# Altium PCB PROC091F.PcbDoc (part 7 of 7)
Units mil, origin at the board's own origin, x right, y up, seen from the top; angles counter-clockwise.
Board outline 3590.95 x 906.17 mil, 8 copper layers (Top Layer, GND1, Sig1, PWR1, PWR2, Sig2, GND2, Bottom Layer), stack 63.146 mil thick; 420 components, 316 nets, 1432 pads, 774 vias.
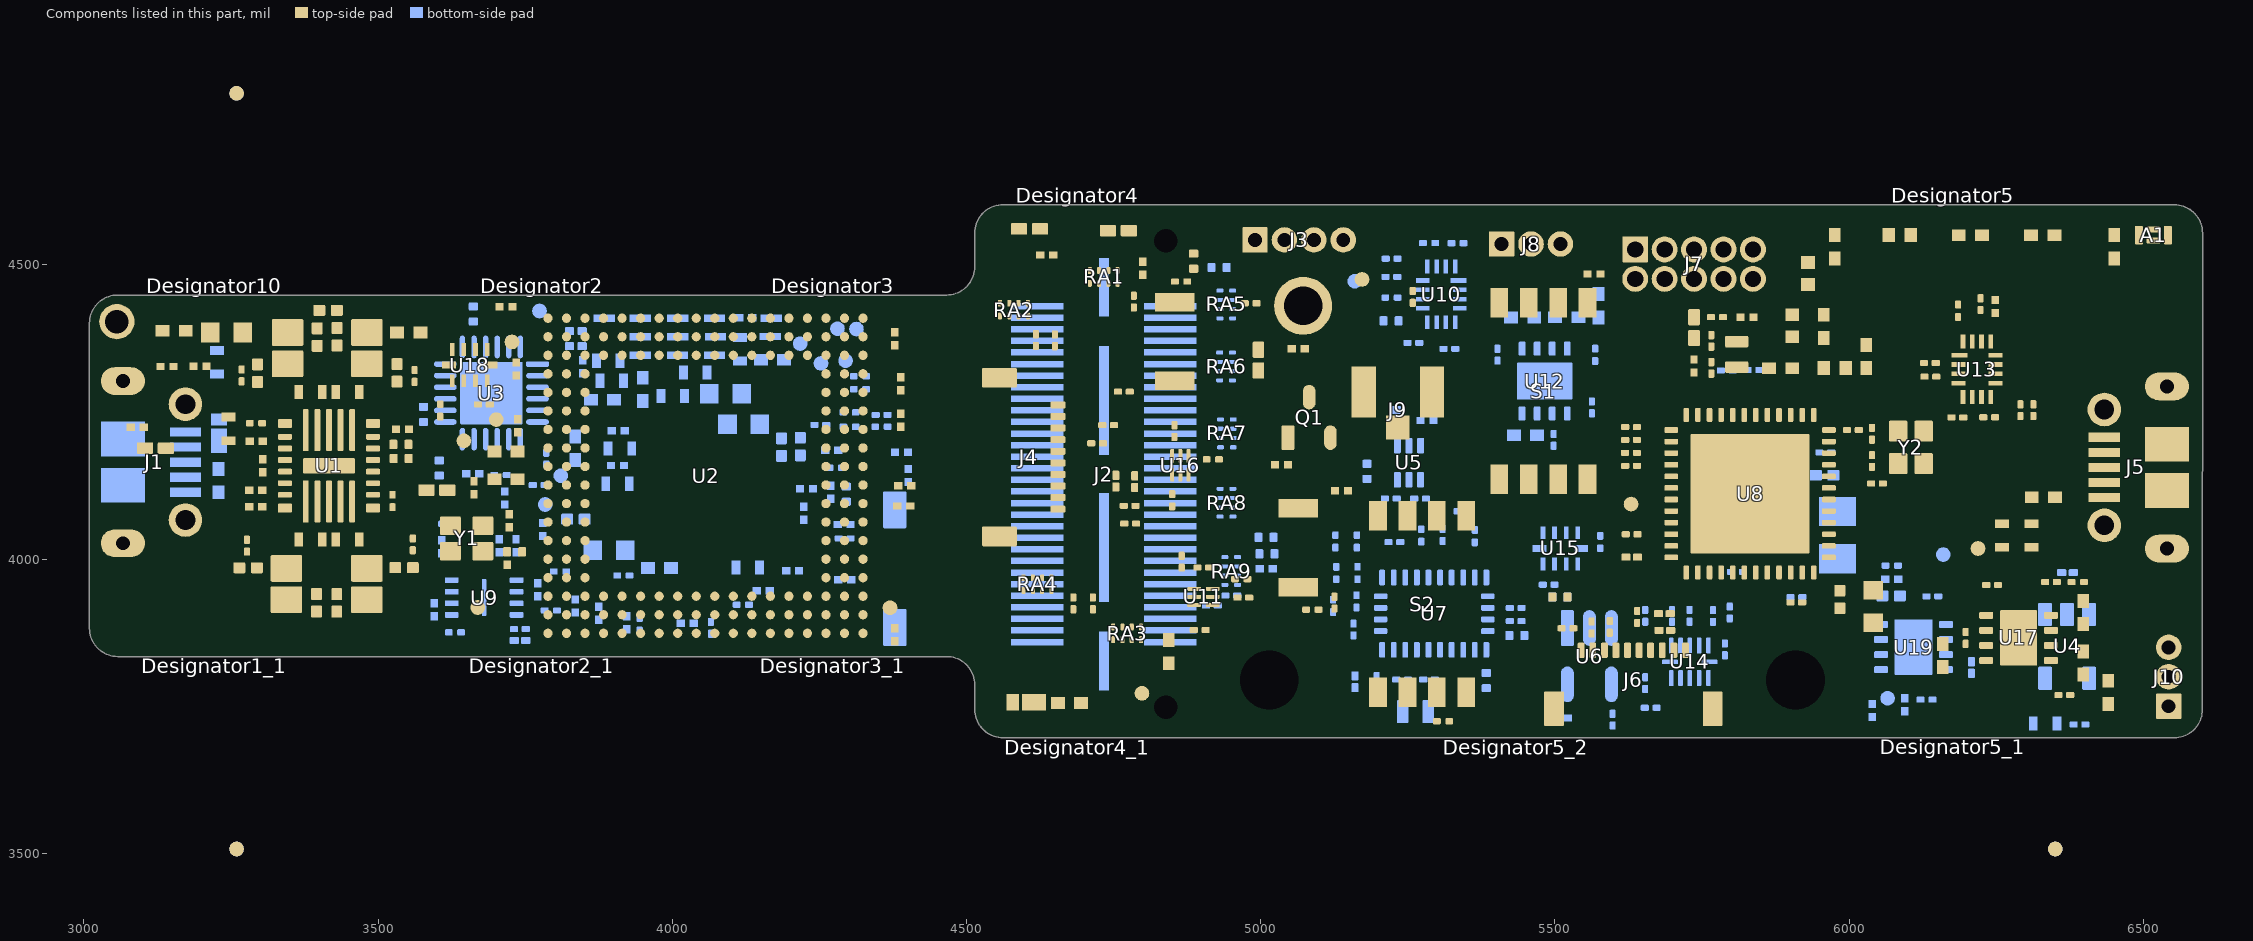
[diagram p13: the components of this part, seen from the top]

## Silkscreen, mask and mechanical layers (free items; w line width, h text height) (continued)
M12 Stackup:
  drawing of 503 lines, arcs and shapes, not listed
  text "Layer" at 8.08,2124.8 h60
  text "Name" at 417.99,2124.8 h60
  text "Material" at 1347.73,2124.8 h60
  text "Thickness" at 2207.5,2124.8 h60
  text "Constant" at 2857.34,2124.8 h60
  text "Board Layer Stack" at 3427.2,2124.8 h60
  text "1" at 8.08,2004.8 h60
  text "Top Overlay" at 417.99,2004.8 h60
  text "2" at 8.08,1884.8 h60
  text "Top Solder" at 417.99,1884.8 h60
  text "Solder Resist" at 1347.73,1884.8 h60
  text "0.50mil" at 2207.5,1884.8 h60
  text "3.5" at 2857.34,1884.8 h60
  text "3" at 8.08,1764.8 h60
  text "Top Layer" at 417.99,1764.8 h60
  text "Copper" at 1347.73,1764.8 h60
  text "1.37mil" at 2207.5,1764.8 h60
  text "4" at 8.08,1644.8 h60
  text "Dielectric1" at 417.99,1644.8 h60
  text "FR-4 High Tg" at 1347.73,1644.8 h60
  text "3.70mil" at 2207.5,1644.8 h60
  text "4.2" at 2857.34,1644.8 h60
  text "5" at 8.08,1524.8 h60
  text "GND1" at 417.99,1524.8 h60
  text "Copper" at 1347.73,1524.8 h60
  text "2.40mil" at 2207.5,1524.8 h60
  text "6" at 8.08,1404.8 h60
  text "Dielectric3" at 417.99,1404.8 h60
  text "FR-4 High Tg" at 1347.73,1404.8 h60
  text "4.50mil" at 2207.5,1404.8 h60
  text "4.2" at 2857.34,1404.8 h60
  text "7" at 8.08,1284.8 h60
  text "Sig1" at 417.99,1284.8 h60
  text "Copper" at 1347.73,1284.8 h60
  text "1.20mil" at 2207.5,1284.8 h60
  text "8" at 8.08,1164.8 h60
  text "Dielectric2" at 417.99,1164.8 h60
  text "FR-4 High Tg" at 1347.73,1164.8 h60
  text "12.00mil" at 2207.5,1164.8 h60
  text "4.2" at 2857.34,1164.8 h60
  text "9" at 8.08,1044.8 h60
  text "PWR1" at 417.99,1044.8 h60
  text "Copper" at 1347.73,1044.8 h60
  text "2.40mil" at 2207.5,1044.8 h60
  text "10" at 8.08,924.8 h60
  text "Dielectric4" at 417.99,924.8 h60
  text "FR-4 High Tg" at 1347.73,924.8 h60
  text "8.00mil" at 2207.5,924.8 h60
  text "4.2" at 2857.34,924.8 h60
  text "11" at 8.08,804.8 h60
  text "PWR2" at 417.99,804.8 h60
  text "Copper" at 1347.73,804.8 h60
  text "2.40mil" at 2207.5,804.8 h60
  text "12" at 8.08,684.8 h60
  text "Dielectric5" at 417.99,684.8 h60
  text "FR-4 High Tg" at 1347.73,684.8 h60
  text "12.00mil" at 2207.5,684.8 h60
  text "4.2" at 2857.34,684.8 h60
  text "13" at 8.08,564.8 h60
  text "Sig2" at 417.99,564.8 h60
  text "Copper" at 1347.73,564.8 h60
  text "1.20mil" at 2207.5,564.8 h60
  text "14" at 8.08,444.8 h60
  text "Dielectric8" at 417.99,444.8 h60
  text "FR-4 High Tg" at 1347.73,444.8 h60
  text "4.50mil" at 2207.5,444.8 h60
  text "4.2" at 2857.34,444.8 h60
  text "15" at 8.08,324.8 h60
  text "GND2" at 417.99,324.8 h60
  text "Copper" at 1347.73,324.8 h60
  text "2.40mil" at 2207.5,324.8 h60
  text "16" at 8.08,204.8 h60
  text "Dielectric9" at 417.99,204.8 h60
  text "FR-4 High Tg" at 1347.73,204.8 h60
  text "3.70mil" at 2207.5,204.8 h60
  text "4.2" at 2857.34,204.8 h60
  text "17" at 8.08,84.8 h60
  text "Bottom Layer" at 417.99,84.8 h60
  text "Copper" at 1347.73,84.8 h60
  text "1.37mil" at 2207.5,84.8 h60
  text "18" at 8.08,-35.2 h60
  text "Bottom Solder" at 417.99,-35.2 h60
  text "Solder Resist" at 1347.73,-35.2 h60
  text "0.50mil" at 2207.5,-35.2 h60
  text "3.5" at 2857.34,-35.2 h60
  text "19" at 8.08,-155.2 h60
  text "Bottom Overlay" at 417.99,-155.2 h60
  text ".Layer_Name" at 577,-858.49 h60
M13 Component Bodies Top:
  text ".Layer_Name" at 577,-858.49 h60
M14 Component Bodies Bottom:
  text ".Layer_Name" at 577,-858.49 h60
M15 Courtyards Top:
  text ".Layer_Name" at 577,-858.49 h60
M16 Courtyards Bottom:
  text ".Layer_Name" at 577,-858.49 h60
Drill Drawing:
  circle w10: c7603.25,4723.45 r16.58
  circle w10: c7603.25,4723.45 r27.63
  circle w10: c7603.25,3355.93 r27.63
  lines w10: 7575.63,3452.62 7603.25,3466.44 7630.88,3452.62 7617.07,3480.25 7630.88,3507.88 7603.25,3494.06 7575.63,3507.88 7589.44,3480.25 7575.63,3452.62 ; 7575.63,3590.76 7589.44,3590.76 7603.25,3576.94 7617.07,3590.76 7630.88,3590.76 7617.07,3604.57 7630.88,3618.38 7617.07,3618.38 7603.25,3632.2 7589.44,3618.38 7575.63,3618.38 7589.44,3604.57 7575.63,3590.76 ; 7575.63,3715.08 7589.44,3715.08 7589.44,3701.26 7617.07,3701.26 7617.07,3715.08 7630.88,3715.08 7630.88,3742.7 7617.07,3742.7 7617.07,3756.52 7589.44,3756.52 7589.44,3742.7 7575.63,3742.7 7575.63,3715.08 ; 7575.63,3825.58 7603.25,3839.4 7630.88,3825.58 7617.07,3853.21 7630.88,3880.84 7603.25,3867.02 7575.63,3880.84 7589.44,3853.21 7575.63,3825.58 ; 7575.63,3977.53 7603.25,3949.9 7630.88,3977.53 7603.25,4005.16 7575.63,3977.53 ; 7575.63,4088.04 7589.44,4088.04 7589.44,4074.22 7617.07,4074.22 7617.07,4088.04 7630.88,4088.04 7630.88,4115.66 7617.07,4115.66 7617.07,4129.48 7589.44,4129.48 7589.44,4115.66 7575.63,4115.66 7575.63,4088.04 ; 7575.63,4253.8 7630.88,4253.8 7603.25,4198.54 7575.63,4253.8 ; 7575.63,4322.86 7575.63,4336.68 7589.44,4350.49 7575.63,4364.3 7575.63,4378.12 7589.44,4378.12 7603.25,4364.3 7617.07,4378.12 7630.88,4378.12 7630.88,4364.3 7617.07,4350.49 7630.88,4336.68 7630.88,4322.86 7617.07,4322.86 7603.25,4336.68 7589.44,4322.86 7575.63,4322.86 ; 7575.63,4447.18 7630.88,4447.18 7630.88,4502.44 7575.63,4502.44 7575.63,4447.18 ; 7575.63,4626.76 7630.88,4626.76 7603.25,4571.5 7575.63,4626.76 ; 7575.63,4820.14 7630.88,4820.14 7630.88,4875.4 7575.63,4875.4 7575.63,4820.14 ; 7586.68,3463.67 7603.25,3471.96 7619.83,3463.67 7611.54,3480.25 7619.83,3496.83 7603.25,3488.54 7586.68,3496.83 7594.97,3480.25 7586.68,3463.67 ; 7586.68,4093.56 7594.97,4093.56 7594.97,4085.27 7611.54,4085.27 7611.54,4093.56 7619.83,4093.56 7619.83,4110.14 7611.54,4110.14 7611.54,4118.43 7594.97,4118.43 7594.97,4110.14 7586.68,4110.14 7586.68,4093.56 ; 7586.68,4615.71 7619.83,4615.71 7603.25,4582.55 7586.68,4615.71 ; 7586.68,4831.19 7619.83,4831.19 7619.83,4864.35 7586.68,4864.35 7586.68,4831.19
  lines w12: 7525.54,3291.01 10757.03,3291.01 ; 7525.54,4907.17 10757.03,4907.17 ; 7863.4,3166.69 7863.4,5031.49 ; 8195.4,3166.69 8195.4,5031.49 ; 8831.96,3166.69 8831.96,5031.49 ; 9091.1,3166.69 9091.1,5031.49 ; 9466.26,3166.69 9466.26,5031.49 ; 10190.59,3166.69 10190.59,5031.49 ; 7525.54,3166.69 10757.03,3166.69 10757.03,5031.49 7525.54,5031.49 7525.54,3166.69
  text "Symbol" at 7600.13,4944.46 h72
  text "Quantity" at 7900.7,4944.46 h72
  text "Finished Hole Size" at 8232.7,4944.46 h72
  text "Plated" at 8869.26,4944.46 h72
  text "Hole Type" at 9128.4,4944.46 h72
  text "Drill Layer Pair" at 9503.56,4944.46 h72
  text "Hole Tolerance" at 10227.89,4944.46 h72
  text "36" at 7900.7,4820.14 h60
  text "7.87mil" at 8232.7,4820.14 h60
  text "PTH" at 8869.26,4820.14 h60
  text "Round" at 9128.4,4820.14 h60
  text "Top Layer - Bottom Layer" at 9503.56,4820.14 h60
  text "626" at 7900.7,4695.82 h60
  text "8.00mil" at 8232.7,4695.82 h60
  text "PTH" at 8869.26,4695.82 h60
  text "Round" at 9128.4,4695.82 h60
  text "Top Layer - Bottom Layer" at 9503.56,4695.82 h60
  text "112" at 7900.7,4571.5 h60
  text "8.00mil" at 8232.7,4571.5 h60
  text "PTH" at 8869.26,4571.5 h60
  text "Round" at 9128.4,4571.5 h60
  text "Top Layer - Bottom Layer" at 9503.56,4571.5 h60
  text "+/-3.00mil" at 10227.89,4571.5 h60
  text "10" at 7900.7,4447.18 h60
  text "23.62mil" at 8232.7,4447.18 h60
  text "PTH" at 8869.26,4447.18 h60
  text "Round" at 9128.4,4447.18 h60
  text "Top Layer - Bottom Layer" at 9503.56,4447.18 h60
  text "4" at 7900.7,4322.86 h60
  text "23.62mil" at 8232.7,4322.86 h60
  text "PTH" at 8869.26,4322.86 h60
  text "Slot" at 9128.4,4322.86 h60
  text "Top Layer - Bottom Layer" at 9503.56,4322.86 h60
  text "10" at 7900.7,4198.54 h60
  text "27.56mil" at 8232.7,4198.54 h60
  text "PTH" at 8869.26,4198.54 h60
  text "Round" at 9128.4,4198.54 h60
  text "Top Layer - Bottom Layer" at 9503.56,4198.54 h60
  text "33" at 7900.7,4074.22 h60
  text "32.00mil" at 8232.7,4074.22 h60
  text "NPTH" at 8869.26,4074.22 h60
  text "Round" at 9128.4,4074.22 h60
  text "Top Layer - Bottom Layer" at 9503.56,4074.22 h60
  text "4" at 7900.7,3949.9 h60
  text "33.47mil" at 8232.7,3949.9 h60
  text "PTH" at 8869.26,3949.9 h60
  text "Round" at 9128.4,3949.9 h60
  text "Top Layer - Bottom Layer" at 9503.56,3949.9 h60
  text "1" at 7900.7,3825.58 h60
  text "40.00mil" at 8232.7,3825.58 h60
  text "PTH" at 8869.26,3825.58 h60
  text "Round" at 9128.4,3825.58 h60
  text "Top Layer - Bottom Layer" at 9503.56,3825.58 h60
  text "2" at 7900.7,3701.26 h60
  text "40.16mil" at 8232.7,3701.26 h60
  text "NPTH" at 8869.26,3701.26 h60
  text "Round" at 9128.4,3701.26 h60
  text "Top Layer - Bottom Layer" at 9503.56,3701.26 h60
  text "1" at 7900.7,3576.94 h60
  text "64.96mil" at 8232.7,3576.94 h60
  text "PTH" at 8869.26,3576.94 h60
  text "Round" at 9128.4,3576.94 h60
  text "Top Layer - Bottom Layer" at 9503.56,3576.94 h60
  text "4" at 7900.7,3452.62 h60
  text "88.00mil" at 8232.7,3452.62 h60
  text "NPTH" at 8869.26,3452.62 h60
  text "Round" at 9128.4,3452.62 h60
  text "Top Layer - Bottom Layer" at 9503.56,3452.62 h60
  text "+/-3.00mil" at 10227.89,3452.62 h60
  text "2" at 7900.7,3328.3 h60
  text "100.00mil" at 8232.7,3328.3 h60
  text "NPTH" at 8869.26,3328.3 h60
  text "Round" at 9128.4,3328.3 h60
  text "Top Layer - Bottom Layer" at 9503.56,3328.3 h60
  text "+/-3.00mil" at 10227.89,3328.3 h60
  text "845 Total" at 7900.7,3203.98 h60
  text "Slot definitions :" at 7600.13,3116.96 h60
  text "Routed Path Length" at 8050.85,3116.96 h60
  text "= Calculated from tool start centre position to tool end centre position." at 8590.58,3116.96 h60
  text "Hole Length" at 8050.85,3067.23 h60
  text "= Routed Path Length + Tool Size = Slot length as defined in the PCB layout" at 8390.78,3067.23 h60
  text ".Layer_Name" at 577,-858.49 h60
M17 Embedded Cavity:
  text ".Layer_Name" at 577,-858.49 h60
M18 Embedded Assembly:
  text ".Layer_Name" at 577,-858.49 h60
M19 Embedded Keepout:
  text ".Layer_Name" at 577,-858.49 h60
Mechanical 21:
  text "Works With TI LaunchPad Logo1" at 56021.02,58034.06 h60
  text "Works With TI LaunchPad Logo1" at 56021.02,58034.06 h60
  text "Logo2" at 54657.52,57702.56 h60
  text "Logo2" at 54657.52,57702.56 h60
  text "LOGO3" at 54889.02,57440.06 h60
  text "LOGO3" at 54889.02,57440.06 h60
  text "FID1" at 55092.65,56736 h60
  text "FID1" at 55092.65,56736 h60
  text "FID2" at 55391.65,56726 h60
  text "FID2" at 55391.65,56726 h60
  text "FID6" at 55107.5,56532.5 h60
  text "FID6" at 55107.5,56532.5 h60
  text "FID5" at 55387.5,56532.5 h60
  text "FID5" at 55387.5,56532.5 h60
  text "FID4" at 55668.5,56532.5 h60
  text "FID4" at 55668.5,56532.5 h60
  text "FID3" at 55948.5,56532.5 h60
  text "FID3" at 55948.5,56532.5 h60
  text "ESD Susceptible1" at 56694.52,56524.06 h60
  text "ESD Susceptible1" at 56694.52,56524.06 h60
  text "CAUTION HOT SURFACE1" at 57228.02,56277.06 h60
  text "CAUTION HOT SURFACE1" at 57228.02,56277.06 h60
  text "For evaluation only; not FCC approved for resale." at 54661.42,56095.48 h60 r90
  text "For evaluation only; not FCC approved for resale." at 54661.42,56095.48 h60 r90
  text "Logo1" at 54419.02,55121.06 h60
  text "Logo1" at 54419.02,55121.06 h60
  text "R73" at 57212.4,54825.61 h60
  text "R73" at 57212.4,54825.61 h60
  text "J17" at 56047,54802 h60
  text "J17" at 56047,54802 h60
  text "J4" at 57338,54802 h60
  text "J4" at 57338,54802 h60
  text "J3" at 58017,54787 h60
  text "J3" at 58017,54787 h60
  text "R14" at 57970,54727 h60
  text "R14" at 57970,54727 h60
  text "Q2" at 58016.76,54608.4 h60
  text "Q2" at 58016.76,54608.4 h60
  text "R128" at 57968,54595 h60
  text "R128" at 57968,54595 h60
  text "DS2" at 58182.15,54571 h60
  text "DS2" at 58182.15,54571 h60
  text "R118" at 58197,54456 h60
  text "R118" at 58197,54456 h60
  text "D4" at 58067.44,54360.39 h60
  text "D4" at 58067.44,54360.39 h60
  text "R351" at 57689,54352 h60
  text "R351" at 57689,54352 h60
  text "R350" at 57689,54300 h60
  text "R350" at 57689,54300 h60
  text "R220" at 57803,54206 h60
  text "R220" at 57803,54206 h60
  text "R223" at 57737.75,53914.35 h60
  text "R223" at 57737.75,53914.35 h60
  text "R227" at 57977.49,53913.76 h60
  text "R227" at 57977.49,53913.76 h60
  text "R190" at 56624.85,53824.59 h60
  text "R190" at 56624.85,53824.59 h60
  text "R189" at 56679.85,53824.59 h60
  text "R189" at 56679.85,53824.59 h60
  text "J15" at 57338.02,53806.06 h60
  text "J15" at 57338.02,53806.06 h60
  text "C66" at 56801.85,53741.59 h60
  text "C66" at 56801.85,53741.59 h60
  text "R67" at 57504.63,53724 h60
  text "R67" at 57504.63,53724 h60
  text "C67" at 56534.85,53719.59 h60
  text "R196" at 56534.85,53719.59 h60
  text "C67" at 56534.85,53719.59 h60
  text "R196" at 56534.85,53719.59 h60
  text "R192" at 56584.85,53719.59 h60
  text "R192" at 56584.85,53719.59 h60
  text "R195" at 56634.85,53719.59 h60
  text "R195" at 56634.85,53719.59 h60
  text "R194" at 56684.85,53719.59 h60
  text "R194" at 56684.85,53719.59 h60
  text "R184" at 56801.85,53719.59 h60
  text "R184" at 56801.85,53719.59 h60
  text "R183" at 56854.85,53719.59 h60
  text "R183" at 56854.85,53719.59 h60
  text "R182" at 56904.85,53719.59 h60
  text "R182" at 56904.85,53719.59 h60
  text "R198" at 56397,53660 h60
  text "R198" at 56397,53660 h60
  text "R70" at 57504.63,53624 h60
  text "R70" at 57504.63,53624 h60
  text "U15" at 56578.85,53601.59 h60
  text "U15" at 56578.85,53601.59 h60
  text "R204" at 57113.07,53589.4 h60
  text "R204" at 57113.07,53589.4 h60
  text "R162" at 56492,53581 h60
  text "R162" at 56492,53581 h60
  text "R60" at 57501,53579 h60
  text "R60" at 57501,53579 h60
  text "R161" at 56492,53544 h60
  text "R161" at 56492,53544 h60
  text "R72" at 57727.07,53524 h60
  text "R72" at 57727.07,53524 h60
  text "R199" at 56330,53492.43 h60
  text "R199" at 56330,53492.43 h60
  text "J10" at 55887,53488 h60
  text "J10" at 55887,53488 h60
  text "R64" at 57718,53480 h60
  text "R64" at 57718,53480 h60
  text "R152" at 57977.49,53479.76 h60
  text "R152" at 57977.49,53479.76 h60
  text "C53" at 57216.92,53466.99 h60
  text "C53" at 57216.92,53466.99 h60
  text "L6" at 57283.85,53449.59 h60
  text "L6" at 57283.85,53449.59 h60
  text "C56" at 57111.85,53444.59 h60
  text "C56" at 57111.85,53444.59 h60
  text "C54" at 57163.92,53444.99 h60
  text "C54" at 57163.92,53444.99 h60
  text "R218" at 56330,53437.43 h60
  text "R218" at 56330,53437.43 h60
  text "R76" at 57727.07,53424 h60
  text "R76" at 57727.07,53424 h60
  text "R200" at 56316.85,53386.59 h60
  text "R200" at 56316.85,53386.59 h60
  text "U7" at 57968.92,53371.46 h60
  text "U7" at 57968.92,53371.46 h60
  text "R81" at 57504.02,53324 h60
  text "R81" at 57504.02,53324 h60
  text "R78" at 57727,53324 h60
  text "R78" at 57727,53324 h60
  text "C36" at 56457.8,53322.99 h60
  text "C36" at 56457.8,53322.99 h60
  text "R201" at 57132.85,53319.59 h60
  text "R201" at 57132.85,53319.59 h60
  text "R206" at 56316.85,53286.59 h60
  text "R206" at 56316.85,53286.59 h60
  text "C52" at 57132.85,53269.59 h60
  text "C52" at 57132.85,53269.59 h60
  text "R207" at 56316.85,53236.59 h60
  text "R207" at 56316.85,53236.59 h60
  text "R85" at 57725,53225 h60
  text "R85" at 57725,53225 h60
  text "C51" at 57131.85,53216.59 h60
  text "C51" at 57131.85,53216.59 h60
  text "R208" at 56316.85,53186.59 h60
  text "R208" at 56316.85,53186.59 h60
  text "R394" at 57716,53187 h60
  text "R394" at 57716,53187 h60
  text "R393" at 57755,53185 h60
  text "R393" at 57755,53185 h60
  text "R61" at 57501,53174 h60
  text "R61" at 57501,53174 h60
  text "L5" at 57153.52,53152.08 h60
  text "L5" at 57153.52,53152.08 h60
  text "C59" at 56452,53137 h60
  text "C59" at 56452,53137 h60
  text "R89" at 57732,53111 h60
  text "R89" at 57732,53111 h60
  text "C58" at 56436.57,53084.4 h60
  text "C58" at 56436.57,53084.4 h60
  text "Y2" at 57122.77,53068.99 h60
  text "Y2" at 57122.77,53068.99 h60
  text "C57" at 56972.85,53059.59 h60
  text "C57" at 56972.85,53059.59 h60
  text "C70" at 56589.23,53056.59 h60
  text "C70" at 56589.23,53056.59 h60
  text "C68" at 56737.85,53056.59 h60
  text "C68" at 56737.85,53056.59 h60
  text "J19" at 58033,53057 h60
  text "J19" at 58033,53057 h60
  text "C69" at 56479.07,53037.4 h60
  text "C69" at 56479.07,53037.4 h60
  text "R90" at 57504.63,53024 h60
  text "R90" at 57504.63,53024 h60
  text "R91" at 57727.07,53024 h60
  text "R91" at 57727.07,53024 h60
  text "R150" at 56532,53006 h60
  text "R150" at 56532,53006 h60
  text "C42" at 56567.65,53006 h60
  text "C42" at 56567.65,53006 h60
  text "C30" at 56412.02,52997.6 h60
  text "C30" at 56412.02,52997.6 h60
  text "R95" at 57721,52978 h60
  text "R95" at 57721,52978 h60
  text "R210" at 56479.85,52975.59 h60
  text "R210" at 56479.85,52975.59 h60
  text "R211" at 56550.85,52975.59 h60
  text "R211" at 56550.85,52975.59 h60
  text "R212" at 56580.85,52975.59 h60
  text "R212" at 56580.85,52975.59 h60
  text "R213" at 56631.85,52975.59 h60
  text "R213" at 56631.85,52975.59 h60
  text "R214" at 56682.85,52975.59 h60
  text "R214" at 56682.85,52975.59 h60
  text "R215" at 56733.85,52975.59 h60
  text "R215" at 56733.85,52975.59 h60
  text "R216" at 56784.85,52975.59 h60
  text "R216" at 56784.85,52975.59 h60
  text "R217" at 56833.85,52975.59 h60
  text "R217" at 56833.85,52975.59 h60
  text "U6" at 56399.87,52935.6 h60
  text "U6" at 56399.87,52935.6 h60
  text "R93" at 57504.63,52924 h60
  text "R93" at 57504.63,52924 h60
  text "R92" at 57727.07,52924 h60
  text "R92" at 57727.07,52924 h60
  text "C29" at 56337.49,52919.55 h60
  text "C29" at 56337.49,52919.55 h60
  text "C28" at 56582,52907 h60
  text "C28" at 56582,52907 h60
  text "R187" at 57077,52877 h60
  text "R187" at 57077,52877 h60
  text "R193" at 57181.62,52877 h60
  text "R193" at 57181.62,52877 h60
  text "C55" at 57312,52877 h60
  text "C55" at 57312,52877 h60
  text "U17" at 56762,52840 h60
  text "U17" at 56762,52840 h60
  text "R185" at 57076.48,52827.58 h60
  text "R185" at 57076.48,52827.58 h60
  text "R186" at 57182,52827 h60
  text "R186" at 57182,52827 h60
  text "R181" at 57312,52827 h60
  text "R181" at 57312,52827 h60
  text "R94" at 57504.63,52824 h60
  text "R94" at 57504.63,52824 h60
  text "C62" at 56584.37,52807.06 h60
  text "C62" at 56584.37,52807.06 h60
  text "R304" at 57236,52750 h60
  text "R304" at 57236,52750 h60
  text "R221" at 56507.09,52747.53 h60
  text "R221" at 56507.09,52747.53 h60
  text "U20" at 57186,52741 h60
  text "U20" at 57186,52741 h60
  text "C65" at 56602,52736.38 h60
  text "C65" at 56602,52736.38 h60
  text "C7" at 57154.28,52735.36 h60
  text "C7" at 57154.28,52735.36 h60
  text "J13" at 56412,52725 h60
  text "J13" at 56412,52725 h60
  text "R306" at 57237,52708 h60
  text "R306" at 57237,52708 h60
  text "SW1" at 57858.65,52699 h60
  text "SW1" at 57858.65,52699 h60
  text "U25" at 56979,52678 h60
  text "U25" at 56979,52678 h60
  text "R310" at 57415,52671 h60
  text "R310" at 57415,52671 h60
  text "R151" at 56897,52642 h60
  text "R151" at 56897,52642 h60
  text "R311" at 57415,52636 h60
  text "R311" at 57415,52636 h60
  text "S7" at 56399,52624 h60
  text "S7" at 56399,52624 h60
  text "R301" at 57372,52599 h60
  text "R301" at 57372,52599 h60
  text "C73" at 56262.62,52569.53 h60
  text "C73" at 56262.62,52569.53 h60
  text "R338" at 56787.37,52555.06 h60
  text "R338" at 56787.37,52555.06 h60
  text "U26" at 56919.12,52539.06 h60
  text "U26" at 56919.12,52539.06 h60
  text "R209" at 56801,52497 h60
  text "R209" at 56801,52497 h60
  text "S10" at 56399,52494 h60
  text "S10" at 56399,52494 h60
  text "C27" at 56283.06,52418 h60
  text "C27" at 56283.06,52418 h60
  text "C50" at 55666,52407 h60
  text "C50" at 55666,52407 h60
  text "S5" at 56399,52381 h60
  text "S5" at 56399,52381 h60
  text "U28" at 56817,52365 h60
  text "U28" at 56817,52365 h60
  text "J14" at 57878.02,52346.06 h60
  text "J14" at 57878.02,52346.06 h60
  text "R24" at 56760,52338 h60
  text "R24" at 56760,52338 h60
  text "U11" at 57728.34,52328.92 h60
  text "U11" at 57728.34,52328.92 h60
  text "R339" at 56204.5,52306.5 h60
  text "R339" at 56204.5,52306.5 h60
  text "S6" at 56399,52288 h60
  text "S6" at 56399,52288 h60
  text "R25" at 56350,52285 h60
  text "R25" at 56350,52285 h60
  text "R16" at 56048,52270.5 h60
  text "R16" at 56048,52270.5 h60
  text "C72" at 55979,52269.62 h60
  text "C72" at 55979,52269.62 h60
  text "R173" at 57089,52231 h60
  text "R173" at 57089,52231 h60
  text "C94" at 56205,52229 h60
  text "C94" at 56205,52229 h60
  text "R18" at 56764,52229 h60
  text "R18" at 56764,52229 h60
  text "U33" at 56923.22,52200.19 h60
  text "U33" at 56923.22,52200.19 h60
  text "U19" at 57072,52191 h60
  text "U19" at 57072,52191 h60
  text "R175" at 57160.32,52177.62 h60
  text "R175" at 57160.32,52177.62 h60
  text "S11" at 56399,52175 h60
  text "S11" at 56399,52175 h60
  text "R41" at 56339.02,52156.06 h60
  text "R41" at 56339.02,52156.06 h60
  text "SW2" at 58116.65,52147 h60
  text "SW2" at 58116.65,52147 h60
  text "R19" at 56771,52133 h60
  text "R19" at 56771,52133 h60
  text "C112" at 56048,52118 h60
  text "C112" at 56048,52118 h60
  text "C117" at 56270.24,52116 h60
  text "C117" at 56270.24,52116 h60
  text "C49" at 57105,52095 h60
  text "C49" at 57105,52095 h60
  text "R180" at 57145,52095 h60
  text "R180" at 57145,52095 h60
  text "R172" at 57063,52089 h60
  text "R172" at 57063,52089 h60
  text "LBL1" at 58550.37,52085.06 h60
  text "LBL1" at 58550.37,52085.06 h60
  text "J9" at 55627.11,52069.11 h60
  text "J9" at 55627.11,52069.11 h60
  text "S3" at 56339,52044 h60
  text "S3" at 56339,52044 h60
  text "R8" at 56993,52019 h60
  text "R8" at 56993,52019 h60
  text "U1" at 56726,52004 h60
  text "U1" at 56726,52004 h60
  text "R229" at 56004.36,51991.59 h60
  text "R229" at 56004.36,51991.59 h60
  text "C2" at 56692,51990.69 h60
  text "C2" at 56692,51990.69 h60
  text "C4" at 57710.2,51977.88 h60
  text "C4" at 57710.2,51977.88 h60
  text "U32" at 56133,51977 h60
  text "U32" at 56133,51977 h60
  text "R1" at 57048,51952 h60
  text "R1" at 57048,51952 h60
  text "R117" at 57862.62,51943.53 h60
  text "R117" at 57862.62,51943.53 h60
  text "R144" at 56003.74,51942.05 h60
  text "R144" at 56003.74,51942.05 h60
  text "R3" at 56919,51937 h60
  text "R3" at 56919,51937 h60
  text "Q1" at 57946.65,51928 h60
  text "Q1" at 57946.65,51928 h60
  text "R261" at 57830.74,51910.17 h60
  text "R261" at 57830.74,51910.17 h60
  text "R54" at 56005,51891 h60
  text "R54" at 56005,51891 h60
  text "DS1" at 58120,51890 h60
  text "DS1" at 58120,51890 h60
  text "C76" at 56572.13,51859.91 h60
  text "C76" at 56572.13,51859.91 h60
  text "S1" at 57770.72,51851 h60
  text "S1" at 57770.72,51851 h60
  text "L7" at 56445.37,51847.06 h60
  text "L7" at 56445.37,51847.06 h60
  text "R270" at 56005,51841 h60
  text "R270" at 56005,51841 h60
  text "R6" at 57000,51841 h60
  text "R6" at 57000,51841 h60
  text "J28" at 56344.97,51821.39 h60
  text "J28" at 56344.97,51821.39 h60
  text "R260" at 57790,51821 h60
  text "R260" at 57790,51821 h60
  text "C111" at 56141.07,51805 h60
  text "C111" at 56141.07,51805 h60
  text "U3" at 56906,51797 h60
  text "U3" at 56906,51797 h60
  text "U12" at 56512.86,51794.81 h60
  text "U12" at 56512.86,51794.81 h60
  text "R269" at 56005,51791 h60
  text "R269" at 56005,51791 h60
  text "R113" at 56205.45,51785.73 h60
  text "R113" at 56205.45,51785.73 h60
  text "J1" at 57964,51782 h60
  text "J1" at 57964,51782 h60
  text "R268" at 56005,51736 h60
  text "R268" at 56005,51736 h60
  text "H2" at 59278.02,51732.06 h60
  text "H2" at 59278.02,51732.06 h60
  text "R256" at 56477.37,51691.06 h60
  text "R256" at 56477.37,51691.06 h60
  text "R30" at 56005,51686 h60
  text "R30" at 56005,51686 h60
  text "R321" at 57316,51648 h60
  text "R321" at 57316,51648 h60
  text "R29" at 56005,51636 h60
  text "R29" at 56005,51636 h60
  text "R324" at 57296,51608 h60
  text "R324" at 57296,51608 h60
  text "Logo4" at 58802.02,51607.06 h60
  text "Logo4" at 58802.02,51607.06 h60
  text "U23" at 57286.85,51605.4 h60
  text "U23" at 57286.85,51605.4 h60
  text "C3" at 57912.37,51605.06 h60
  text "C3" at 57912.37,51605.06 h60
  text "C26" at 57052.91,51598.66 h60
  text "C26" at 57052.91,51598.66 h60
  text "H1" at 58428.02,51592.06 h60
  text "H1" at 58428.02,51592.06 h60
  text "R28" at 56005,51581 h60
  text "R28" at 56005,51581 h60
  text "R313" at 56661.74,51578.44 h60
  text "R313" at 56661.74,51578.44 h60
  text "R331" at 57329.82,51571.99 h60
  text "R331" at 57329.82,51571.99 h60
  text "D11" at 56775.76,51570.07 h60
  text "D11" at 56775.76,51570.07 h60
  text "R291" at 56531,51569 h60
  text "R291" at 56531,51569 h60
  text "C81" at 57580,51554 h60
  text "C81" at 57580,51554 h60
  text "R317" at 57316.07,51536.47 h60
  text "R317" at 57316.07,51536.47 h60
  text "R27" at 56005,51531 h60
  text "R27" at 56005,51531 h60
  text "L9" at 56729,51530 h60
  text "L9" at 56729,51530 h60
  text "P1" at 56364.86,51510 h60
  text "P1" at 56364.86,51510 h60
  text "R396" at 56236,51508 h60
  text "R396" at 56236,51508 h60
  text "R332" at 57303,51501 h60
  text "R332" at 57303,51501 h60
  text "R397" at 56156,51488 h60
  text "R397" at 56156,51488 h60
  text "R21" at 56005,51481 h60
  text "R21" at 56005,51481 h60
  text "C120" at 56233,51472 h60
  text "C120" at 56233,51472 h60
  text "U30" at 56169,51440 h60
  text "U30" at 56169,51440 h60
  text "R20" at 56005,51431 h60
  text "R20" at 56005,51431 h60
  text "R271" at 57433.29,51414.06 h60
  text "R271" at 57433.29,51414.06 h60
  text "C82" at 57571,51411 h60
  text "C82" at 57571,51411 h60
  text "R395" at 56133.32,51388.04 h60
  text "R395" at 56133.32,51388.04 h60
  text "R246" at 56005,51381 h60
  text "R246" at 56005,51381 h60
  text "C78" at 57741,51368 h60
  text "C78" at 57741,51368 h60
  text "J2" at 57964,51337 h60
  text "J2" at 57964,51337 h60
  text "R243" at 56005,51331 h60
  text "R243" at 56005,51331 h60
  text "L8" at 57711,51315 h60
  text "L8" at 57711,51315 h60
  text "R309" at 56935.21,51298.07 h60
  text "R309" at 56935.21,51298.07 h60
  text "U13" at 57467,51295 h60
  text "U13" at 57467,51295 h60
  text "C88" at 56223,51294 h60
  text "C88" at 56223,51294 h60
  text "C108" at 56561,51275 h60
  text "C108" at 56561,51275 h60
  text "U29" at 56752,51266 h60
  text "U29" at 56752,51266 h60
  text "J27" at 56378.3,51228.62 h60
  text "J27" at 56378.3,51228.62 h60
  text "R115" at 56222.08,51202.58 h60
  text "R115" at 56222.08,51202.58 h60
  text "C99" at 57036,51199 h60
  text "C99" at 57036,51199 h60
  text "H3" at 59278.02,51192.06 h60
  text "H3" at 59278.02,51192.06 h60
  text "C100" at 56947,51182 h60
  text "C100" at 56947,51182 h60
  text "H4" at 59658.02,51182.06 h60
  text "H4" at 59658.02,51182.06 h60
  text "H5" at 60008.02,51182.06 h60
  text "H5" at 60008.02,51182.06 h60
  text "U31" at 56061,51181 h60
  text "U31" at 56061,51181 h60
  text "C102" at 56496,51175 h60
  text "C102" at 56496,51175 h60
  text "H6" at 60368.02,51172.06 h60
  text "H6" at 60368.02,51172.06 h60
  text "C103" at 56629,51171 h60
  text "C103" at 56629,51171 h60
  text "C87" at 57290,51136 h60
  text "C87" at 57290,51136 h60
  text "R318" at 58884.02,51117.68 h60
  text "R318" at 58884.02,51117.68 h60
  text "R315" at 58534.02,51114.06 h60
  text "R315" at 58534.02,51114.06 h60
  text "C91" at 57811,51090 h60
  text "C91" at 57811,51090 h60
  text "R131" at 55699.43,51041.54 h60
  text "R131" at 55699.43,51041.54 h60
  text "C97" at 56692.79,51024.94 h60
  text "C97" at 56692.79,51024.94 h60
  text "C109" at 56067,50998 h60
  text "C109" at 56067,50998 h60
  text "R140" at 55967.43,50996.54 h60
  text "R140" at 55967.43,50996.54 h60
  text "R133" at 55707.43,50987.54 h60
  text "R133" at 55707.43,50987.54 h60
  text "R139" at 55829.43,50987.54 h60
  text "R139" at 55829.43,50987.54 h60
  text "C79" at 57637.52,50972.56 h60
  text "C79" at 57637.52,50972.56 h60
  text "R135" at 55624.43,50940.54 h60
  text "R135" at 55624.43,50940.54 h60
  text "R136" at 55745.43,50940.54 h60
  text "R136" at 55745.43,50940.54 h60
  text "R141" at 55876.43,50932.54 h60
  text "R141" at 55876.43,50932.54 h60
  text "R134" at 55707.43,50906.54 h60
  text "R134" at 55707.43,50906.54 h60
  text "R138" at 55829.43,50906.54 h60
  text "R138" at 55829.43,50906.54 h60
  text "R132" at 55625.43,50905.54 h60
  text "R132" at 55625.43,50905.54 h60
  text "R137" at 55745.43,50905.54 h60
  text "R137" at 55745.43,50905.54 h60
  text "R143" at 55876.43,50897.54 h60
  text "R143" at 55876.43,50897.54 h60
  text "R116" at 57765.62,50891.53 h60
  text "R116" at 57765.62,50891.53 h60
  text "P7" at 57484.37,50880.06 h60
  text "P7" at 57484.37,50880.06 h60
  text "P3" at 57606.37,50880.06 h60
  text "P3" at 57606.37,50880.06 h60
  text "TP1" at 57933.94,50875.28 h60
  text "TP1" at 57933.94,50875.28 h60
  text "D14" at 58099.72,50838 h60
  text "D14" at 58099.72,50838 h60
  text "P4" at 55566,50798.61 h60
  text "P4" at 55566,50798.61 h60
  text "J18" at 55787.63,50773.94 h60
  text "J18" at 55787.63,50773.94 h60
  text "J20" at 56602.63,50773.94 h60
  text "J20" at 56602.63,50773.94 h60
  text "P2" at 57944,50712.02 h60
  text "P2" at 57944,50712.02 h60
  text "C23" at 57473,50628 h60
  text "C23" at 57473,50628 h60
  text "F1" at 57792,50601 h60
  text "F1" at 57792,50601 h60
  text "P5" at 55566,50598.75 h60
  text "P5" at 55566,50598.75 h60
  text "J16" at 55938,50552 h60
  text "J16" at 55938,50552 h60
  text "R142" at 56107.74,50443.95 h60 r90
  text "R142" at 56107.74,50443.95 h60 r90
  text "P6" at 55566,50401 h60
  text "P6" at 55566,50401 h60
  text "D1" at 57757.37,50398.06 h60
  text "D1" at 57757.37,50398.06 h60
  text "D8" at 56409.81,50257.81 h60
  text "D8" at 56409.81,50257.81 h60
  text "DS4" at 55968,50257 h60
  text "DS4" at 55968,50257 h60
  text "DS3" at 56037,50256 h60
  text "DS3" at 56037,50256 h60
  text "D6" at 56255,50256 h60
  text "D6" at 56255,50256 h60
  text "D10" at 55995,50254.54 h60
  text "D10" at 55995,50254.54 h60
  text "D9" at 56115,50254.54 h60
  text "D9" at 56115,50254.54 h60
  text "D5" at 56185,50254.54 h60
  text "D5" at 56185,50254.54 h60
  text "D7" at 56329.19,50254.54 h60
  text "D7" at 56329.19,50254.54 h60

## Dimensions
3057.58,4448.76 to 3057.58,3834.46 on M2 Board Dimensions
4514.15,4554.37 to 6600.53,4554.1 on M2 Board Dimensions
6552.53,4602.08 to 6552.27,3696.2 on M2 Board Dimensions
3009.58,3455.37 to 6600.3,3455.37 on M2 Board Dimensions
4466.36,3957.89 to 3922,3330 on M2 Board Dimensions
4489.12,3932.89 to 4466.36,4007.54 on M2 Board Dimensions
4514.12,3982.54 to 4441.36,3957.89 on M2 Board Dimensions
6552.3,3455.37 to 6655,3165 on M2 Board Dimensions
3057.58,3407.37 to 3057.58,4891.47 on M2 Board Dimensions
3057.58,3407.37 to 3060,4541.26 on M2 Board Dimensions
3057.58,3407.37 to 3057.58,4448.76 on M2 Board Dimensions
3057.58,3407.37 to 3057.58,3834.46 on M2 Board Dimensions
3057.58,3407.37 to 3060,3741.94 on M2 Board Dimensions
4510.32,3943.73 to 5338.56,3037.37 on M10 Fab Notes
4506.81,4113.64 to 5338.56,3037.37 on M10 Fab Notes
4477.75,4291.3 to 5338.56,3037.37 on M10 Fab Notes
